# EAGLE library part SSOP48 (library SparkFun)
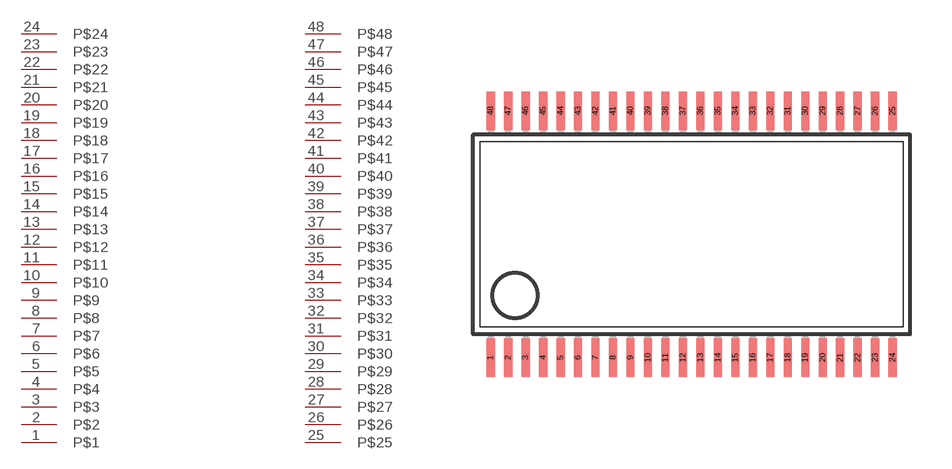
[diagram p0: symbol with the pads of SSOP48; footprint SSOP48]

Designator prefix -

## SSOP48  [SSOP48]
1  P$1
2  P$2
3  P$3
4  P$4
5  P$5
6  P$6
7  P$7
8  P$8
9  P$9
10  P$10
11  P$11
12  P$12
13  P$13
14  P$14
15  P$15
16  P$16
17  P$17
18  P$18
19  P$19
20  P$20
21  P$21
22  P$22
23  P$23
24  P$24
25  P$25
26  P$26
27  P$27
28  P$28
29  P$29
30  P$30
31  P$31
32  P$32
33  P$33
34  P$34
35  P$35
36  P$36
37  P$37
38  P$38
39  P$39
40  P$40
41  P$41
42  P$42
43  P$43
44  P$44
45  P$45
46  P$46
47  P$47
48  P$48

## Footprint SSOP48 (pad centres in mm)
smd 0.305 x 1.397: 1 0.318,0.597; 2 0.953,0.597; 3 1.587,0.597; 4 2.223,0.597; 5 2.857,0.597; 6 3.493,0.597; 7 4.128,0.597; 8 4.763,0.597; 9 5.397,0.597; 10 6.032,0.597; 11 6.668,0.597; 12 7.303,0.597; 13 7.938,0.597; 14 8.572,0.597; 15 9.207,0.597; 16 9.842,0.597; 17 10.477,0.597; 18 11.113,0.597; 19 11.748,0.597; 20 12.383,0.597; 21 13.018,0.597; 22 13.652,0.597; 23 14.287,0.597; 24 14.922,0.597; 25 14.922,9.563; 26 14.287,9.563; 27 13.652,9.563; 28 13.018,9.563; 29 12.383,9.563; 30 11.748,9.563; 31 11.113,9.563; 32 10.477,9.563; 33 9.842,9.563; 34 9.207,9.563; 35 8.572,9.563; 36 7.938,9.563; 37 7.303,9.563; 38 6.668,9.563; 39 6.032,9.563; 40 5.397,9.563; 41 4.763,9.563; 42 4.128,9.563; 43 3.493,9.563; 44 2.857,9.563; 45 2.223,9.563; 46 1.587,9.563; 47 0.953,9.563; 48 0.318,9.563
